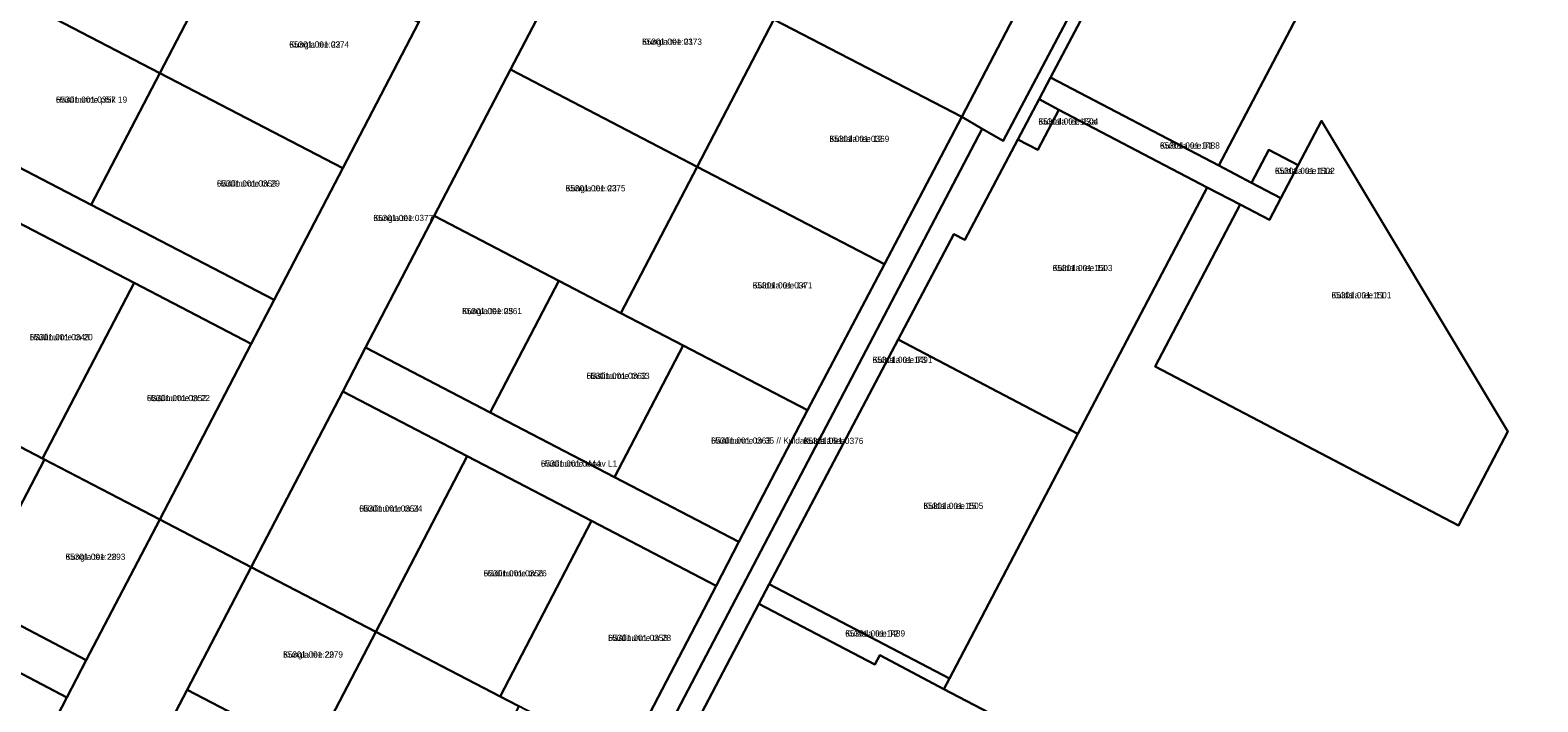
# Model space of a CAD drawing. Extents: x 543236 to 563717, y 6566033 to 6588992.
# Drawn here: x 545424.5 to 545789.8, y 6585243.3 to 6585406.3 of the extents above; entities that cross this region are included whole.
import ezdxf

# ---------------------------------------------------------------- set-up
doc = ezdxf.new("R2010")
doc.units = 0
for name, color, linetype in [('L_AADRESS', 7, 'Continuous'), ('PIIR', 7, 'Continuous'), ('TUNNUS', 7, 'Continuous')]:
    doc.layers.add(name, color=color, linetype=linetype)

msp = doc.modelspace()

# ---------------------------------------------------------------- linework, layer by layer
at = {"layer": 'PIIR'}
for points in [[(545655.16, 6585382.35), (545650.21, 6585385.19), (545709.21, 6585498.57), (545732.07, 6585543.02), (545757.61, 6585595.19), (545765.7, 6585608.98), (545771.49, 6585619.02), (545773.55, 6585622.49), (545777.76, 6585629.74), (545801.37, 6585675.11), (545824.31, 6585718.82), (545831.07, 6585736.04), (545833.4, 6585747.53), (545837.82, 6585740.92), (545816.24, 6585689.82), (545816.46, 6585689.47), (545795.07, 6585646.4), (545775.69, 6585602.66), (545761.29, 6585574.22), (545731.03, 6585514.44), (545720.06, 6585492.78), (545700.59, 6585455.88), (545678.51, 6585414.04), (545660.23, 6585379.39)], [(545561.58, 6585431.12), (545559.39, 6585432.3), (545598.51, 6585503.68), (545621.51, 6585548.98), (545657.89, 6585527.49), (545709.21, 6585498.57), (545650.21, 6585385.19), (545604.66, 6585408.81)], [(545700.59, 6585455.88), (545743.84, 6585433.2), (545712.47, 6585373.43), (545671.71, 6585394.8), (545681.17, 6585412.64), (545678.51, 6585414.04)], [(545422.14, 6585413.39), (545440.61, 6585448.87), (545474.32, 6585431.32), (545455.84, 6585395.84)], [(545455.85, 6585287.6), (545478.02, 6585330.17), (545483.56, 6585340.81), (545500.19, 6585372.74), (545518.66, 6585408.22), (545537.19, 6585444.1), (545559.39, 6585432.3), (545540.84, 6585396.67), (545522.36, 6585361.2), (545505.73, 6585329.27), (545500.19, 6585318.62), (545478.02, 6585276.05)], [(545455.84, 6585395.84), (545474.32, 6585431.32), (545518.66, 6585408.22), (545500.19, 6585372.74)], [(545540.84, 6585396.67), (545559.39, 6585432.3), (545561.58, 6585431.12), (545604.66, 6585408.81), (545586.07, 6585373.12)], [(545405.51, 6585381.46), (545422.14, 6585413.39), (545455.84, 6585395.84), (545439.21, 6585363.91)], [(545576.01, 6585231.19), (545655.16, 6585382.35), (545660.23, 6585379.39), (545678.51, 6585414.04), (545681.17, 6585412.64), (545671.71, 6585394.8), (545668.91, 6585389.49), (545663.77, 6585379.74), (545650.9, 6585355.37), (545648.25, 6585356.76), (545634.76, 6585331.19), (545603.5, 6585271.93), (545601, 6585267.13), (545583.64, 6585234.01), (545586.14, 6585225.85)], [(545586.07, 6585373.12), (545604.66, 6585408.81), (545650.21, 6585385.19), (545631.44, 6585349.49)], [(545439.21, 6585363.91), (545455.84, 6585395.84), (545500.19, 6585372.74), (545483.56, 6585340.81)], [(545522.36, 6585361.2), (545540.84, 6585396.67), (545586.07, 6585373.12), (545567.6, 6585337.64), (545552.52, 6585345.49)], [(545671.71, 6585394.8), (545712.47, 6585373.43), (545720.43, 6585369.26), (545727.52, 6585365.54), (545724.73, 6585360.23), (545717.64, 6585363.94), (545709.67, 6585368.12), (545673.73, 6585386.96), (545668.91, 6585389.49)], [(545668.91, 6585389.49), (545673.73, 6585386.96), (545668.59, 6585377.2), (545663.77, 6585379.74)], [(545573.51, 6585226.42), (545568.52, 6585229.01), (545590.66, 6585271.51), (545596.2, 6585282.16), (545612.83, 6585314.09), (545631.44, 6585349.49), (545650.21, 6585385.19), (545655.16, 6585382.35), (545576.01, 6585231.19)], [(545663.77, 6585379.74), (545668.59, 6585377.2), (545673.73, 6585386.96), (545709.67, 6585368.12), (545678.33, 6585308.34), (545634.76, 6585331.19), (545648.25, 6585356.76), (545650.9, 6585355.37)], [(545737.33, 6585384.25), (545782.51, 6585308.92), (545770.56, 6585286.13), (545697.05, 6585324.68), (545717.64, 6585363.94), (545724.73, 6585360.23), (545727.52, 6585365.54), (545731.7, 6585373.51)], [(545720.43, 6585369.26), (545724.61, 6585377.23), (545731.7, 6585373.51), (545727.52, 6585365.54)], [(545567.6, 6585337.64), (545586.07, 6585373.12), (545631.44, 6585349.49), (545612.83, 6585314.09), (545582.67, 6585329.79)], [(545399.08, 6585317.16), (545421.25, 6585359.73), (545449.64, 6585344.95), (545427.47, 6585302.38)], [(545505.73, 6585329.27), (545522.36, 6585361.2), (545552.52, 6585345.49), (545535.89, 6585313.56)], [(545427.47, 6585302.38), (545449.64, 6585344.95), (545478.02, 6585330.17), (545455.85, 6585287.6)], [(545535.89, 6585313.56), (545552.52, 6585345.49), (545567.6, 6585337.64), (545582.67, 6585329.79), (545566.05, 6585297.86)], [(545500.19, 6585318.62), (545505.73, 6585329.27), (545535.89, 6585313.56), (545566.05, 6585297.86), (545596.2, 6585282.16), (545590.66, 6585271.51), (545560.5, 6585287.22), (545530.35, 6585302.92)], [(545566.05, 6585297.86), (545582.67, 6585329.79), (545612.83, 6585314.09), (545596.2, 6585282.16)], [(545634.76, 6585331.19), (545678.33, 6585308.34), (545647.21, 6585249.01), (545603.5, 6585271.93)], [(545478.02, 6585276.05), (545500.19, 6585318.62), (545530.35, 6585302.92), (545508.18, 6585260.35)], [(545400.14, 6585316.61), (545427.47, 6585302.38), (545427.9, 6585302.15), (545410.19, 6585268.12), (545382.43, 6585282.6)], [(545427.9, 6585302.15), (545455.85, 6585287.6), (545438.07, 6585253.45), (545410.19, 6585268.12)], [(545508.18, 6585260.35), (545530.35, 6585302.92), (545560.5, 6585287.22), (545538.33, 6585244.64)], [(545372.6, 6585274.21), (545378.14, 6585284.85), (545382.43, 6585282.6), (545410.19, 6585268.12), (545438.07, 6585253.45), (545433.36, 6585244.41), (545402.76, 6585260.48), (545392.06, 6585266.04), (545383.37, 6585268.57)], [(545455.85, 6585287.6), (545478.02, 6585276.05), (545462.53, 6585246.3), (545457.82, 6585237.26), (545444.19, 6585211.09), (545430.7, 6585185.18), (545415.55, 6585156.09), (545399.99, 6585126.22), (545377.89, 6585137.91), (545394.95, 6585170.65), (545416.76, 6585212.53), (545433.36, 6585244.41), (545438.07, 6585253.45)], [(545538.33, 6585244.64), (545560.5, 6585287.22), (545590.66, 6585271.51), (545568.52, 6585229.01)], [(545478.02, 6585276.05), (545508.18, 6585260.35), (545493.48, 6585232.12), (545486.61, 6585235.72), (545480.17, 6585237.06), (545462.53, 6585246.3)], [(545603.5, 6585271.93), (545647.21, 6585249.01), (545645.88, 6585246.47), (545630.3, 6585254.64), (545629.11, 6585252.39), (545601, 6585267.13)], [(545601, 6585267.13), (545629.11, 6585252.39), (545630.3, 6585254.64), (545645.88, 6585246.47), (545682.55, 6585227.24), (545660.76, 6585185.7), (545586.14, 6585225.85), (545583.64, 6585234.01)], [(545402.76, 6585260.48), (545433.36, 6585244.41), (545416.76, 6585212.53), (545386.12, 6585228.55)], [(545508.18, 6585260.35), (545538.33, 6585244.64), (545542.85, 6585242.29), (545528.15, 6585214.06), (545497.44, 6585230.04), (545493.48, 6585232.12)], [(545462.53, 6585246.3), (545480.17, 6585237.06), (545486.61, 6585235.72), (545493.48, 6585232.12), (545497.44, 6585230.04), (545491.9, 6585219.4), (545457.82, 6585237.26)]]:
    msp.add_lwpolyline(points, close=True, dxfattribs=at)
for points in [[(545810.82, 6585238.87), (545779.7, 6585179.53), (545778.37, 6585177), (545741, 6585196.59), (545682.55, 6585227.24), (545645.88, 6585246.47), (545647.21, 6585249.01), (545678.33, 6585308.34), (545709.67, 6585368.12), (545717.64, 6585363.94), (545697.05, 6585324.68), (545770.56, 6585286.13), (545782.51, 6585308.92), (545737.33, 6585384.25), (545731.7, 6585373.51), (545724.61, 6585377.23), (545720.43, 6585369.26), (545712.47, 6585373.43), (545743.84, 6585433.2)], [(545405.51, 6585381.46), (545439.21, 6585363.91), (545483.56, 6585340.81), (545478.02, 6585330.17), (545449.64, 6585344.95), (545421.25, 6585359.73)]]:
    msp.add_lwpolyline(points, dxfattribs=at)

# ---------------------------------------------------------------- texts
at = {"layer": 'L_AADRESS'}
for s, p in [('Kungla tee 22', (545487.25, 6585402.03)), ('Kungla tee 21', (545572.73, 6585402.71)), ('Häälinurme põik 19', (545430.68, 6585388.65)), ('Kuldala tee 13a', (545668.75, 6585383.35)), ('Kuldala tee 12', (545618.12, 6585379.15)), ('Kuldala tee T1', (545698.21, 6585377.52)), ('Kuldala tee 11a', (545726.07, 6585371.38)), ('Häälinurme tn 29', (545469.7, 6585368.32)), ('Kungla tee 23', (545554.21, 6585367.16)), ('Kungla tee', (545507.62, 6585359.96)), ('Kuldala tee 13', (545672.21, 6585347.82)), ('Kuldala tee 14', (545599.53, 6585343.61)), ('Kuldala tee 11', (545739.78, 6585341.22)), ('Kungla tee 25', (545529.12, 6585337.38)), ('Häälinurme tn 20', (545424.36, 6585331.05)), ('Kuldala tee T3', (545628.59, 6585325.55)), ('Häälinurme tn 33', (545559.28, 6585321.68)), ('Häälinurme tn 22', (545452.75, 6585316.28)), ('Häälinurme tn 35 // Kuldala tee 16', (545589.44, 6585305.97)), ('Kuldala tee', (545611.84, 6585305.9)), ('Häälinurme tänav L1', (545548.2, 6585300.39)), ('Häälinurme tn 24', (545504.19, 6585289.49)), ('Kuldala tee 15', (545640.91, 6585290.14)), ('Kungla tee 28', (545433.02, 6585277.8)), ('Häälinurme tn 26', (545534.34, 6585273.78)), ('Häälinurme tn 28', (545564.49, 6585258.12)), ('Kuldala tee T2', (545621.95, 6585259.2)), ('Kungla tee 29', (545485.75, 6585254.09))]:
    msp.add_text(s, height=1.5, dxfattribs=at).set_placement(p)
at = {"layer": 'TUNNUS'}
for s, p in [('65301:001:0374', (545487.25, 6585402.03)), ('65301:001:0373', (545572.73, 6585402.71)), ('65301:001:0357', (545430.68, 6585388.65)), ('65301:001:1504', (545668.75, 6585383.35)), ('65301:001:0369', (545618.12, 6585379.15)), ('65301:001:1488', (545698.21, 6585377.52)), ('65301:001:1502', (545726.07, 6585371.38)), ('65301:001:0359', (545469.7, 6585368.32)), ('65301:001:0375', (545554.21, 6585367.16)), ('65301:001:0377', (545507.62, 6585359.96)), ('65301:001:1503', (545672.21, 6585347.82)), ('65301:001:0371', (545599.53, 6585343.61)), ('65301:001:1501', (545739.78, 6585341.22)), ('65301:001:0361', (545529.12, 6585337.38)), ('65301:001:0348', (545424.36, 6585331.05)), ('65301:001:1491', (545628.59, 6585325.55)), ('65301:001:0362', (545559.28, 6585321.68)), ('65301:001:0352', (545452.75, 6585316.28)), ('65301:001:0363', (545589.44, 6585305.97)), ('65301:001:0376', (545611.84, 6585305.9)), ('65301:001:0444', (545548.2, 6585300.39)), ('65301:001:0354', (545504.19, 6585289.49)), ('65301:001:1505', (545640.91, 6585290.14)), ('65301:001:2293', (545433.02, 6585277.8)), ('65301:001:0356', (545534.34, 6585273.78)), ('65301:001:0358', (545564.49, 6585258.12)), ('65301:001:1489', (545621.95, 6585259.2)), ('65301:001:2279', (545485.75, 6585254.09))]:
    msp.add_text(s, height=1.5, dxfattribs=at).set_placement(p)

doc.saveas('drawing.dxf')
